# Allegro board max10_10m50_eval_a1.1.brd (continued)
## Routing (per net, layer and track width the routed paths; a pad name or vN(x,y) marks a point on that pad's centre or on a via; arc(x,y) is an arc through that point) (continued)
OV10640_CMOS_SCLK: length 57.4
  TOP w0.147: U1.P5 v1(49.51,35.46)
  ART04 w0.109: v1(49.51,35.46) 50.05,34.92 52.96,34.92 53.89,33.99 53.89,23.83 54.36,23.37 54.36,22.73 54.66,22.43 60.15,22.43 60.71,22.99 65.15,22.99 69.34,18.8 69.34,17.4 69.85,16.89 74.68,16.89 75.44,17.65 80.39,17.65 81.41,18.67 82.93,18.67 83.69,19.43 83.69,20.57 v2(82.55,21.72)
  BOTTOM w0.147: J2.25 81.48,22.15 81.92,21.72 v2(82.55,21.72) R92.2
OV10640_CMOS_SDATA: length 44.4
  TOP w0.147: U1.N8 v1(52.51,35.46)
  ART04 w0.109: v1(52.51,35.46) 52.89,35.84 53.82,35.84 53.98,35.69 53.98,35.43 54.89,34.52 54.89,32.38 55.27,32 55.75,32 55.89,31.87 55.89,29.47 54.74,28.32 54.74,24.51 55.37,23.88 65.66,23.88 67.56,21.97 67.56,21.46 71.25,17.78 v2(73.03,17.78)
  BOTTOM w0.147: J2.24 76.37,22.65 75.31,21.59 75.31,21.08 74.42,20.19 R89.2 73.6,19.81 72.77,18.99 72.77,18.03 v2(73.03,17.78)
OV10640_DATA_HS_N1: length 24.2
  TOP w0.132: U1.AB21 66.02,26.8 66.47,26.34 67.24,26.34 67.36,26.47 67.7,26.47 67.82,26.34 68,26.34 68.4,26.74 68.4,27.23 68.17,27.46 68.17,27.79 68.4,28.01 68.4,28.3 68.17,28.52 68.17,28.88 68.4,29.11 68.4,29.31 68.17,29.54 68.17,29.9 68.4,30.12 68.4,30.45 68.17,30.68 68.17,31.1 68.58,31.5 68.58,31.88 68.83,32.13 69.23,32.13 69.47,32.37 69.47,32.66 69.7,32.89 69.99,32.89 70.28,33.17 70.87,33.17 70.97,33.27 71.37,33.27 71.47,33.17 72.74,33.17 R83.1 73.7,33.17 73.94,33.17 v1(74.3,33.53) 74.62,33.2 75.87,33.2 78.29,30.79 78.67,30.79 v1(78.74,30.86)
  BOTTOM w0.132: v1(78.74,30.86) 79.25,30.35 79.94,30.35 J2.9 ; R86.1 73.6,33.52 73.85,33.27 74.04,33.27 v1(74.3,33.53)
OV10640_DATA_HS_N2: length 25.3
  TOP w0.132: v1(78.61,27.05) 78.49,27.18 78.11,27.18 76.71,25.78 75.69,25.78 75.13,26.34 75.13,27.12 74.95,27.3 74.55,27.3 v1(74.3,27.05) 73.94,27.4 73.7,27.4 R90.1 72.74,27.4 70.31,27.4 70.1,27.2 70.1,26.03 68.45,24.38 66.04,24.38 65.15,23.49 64.39,23.49 63.75,24.13 63.75,25.21 64.25,25.71 64.25,26.73 U1.AB19
  BOTTOM w0.132: v1(74.3,27.05) 74.04,27.3 73.72,27.3 R93.1 ; v1(78.61,27.05) 78.71,27.15 J2.15
OV10640_DATA_HS_N3: length 27
  TOP w0.132: U1.AB17 62.3,26.68 62.3,23.44 63.32,22.42 63.77,21.97 65.53,21.97 66.24,22.68 67,22.68 67.71,21.97 68.45,21.97 69.72,23.24 69.72,23.88 70.58,24.74 72.74,24.74 R76.1 73.7,24.74 73.94,24.74 v1(74.3,24.38) 74.63,24.72 74.87,24.72 75.84,23.75 76.45,23.75 78.2,25.5 78.51,25.5 v1(78.61,25.4)
  BOTTOM w0.132: v1(78.61,25.4) 78.1,25.91 77.6,25.91 J2.18 ; v1(74.3,24.38) 74.04,24.64 73.72,24.64 R78.1
OV10640_DATA_HS_N4: length 28.2
  TOP w0.132: U1.AB16 61.05,26.93 61.05,26.38 60.83,26.16 60.83,25.87 61.05,25.65 61.05,25.27 60.83,25.06 60.83,24.72 61.05,24.51 61.05,22.9 61.85,22.1 61.85,21.84 62.23,21.46 62.48,21.46 63.3,20.65 68.91,20.65 70.33,22.07 72.74,22.07 R84.1 73.7,22.07 73.94,22.07 v1(74.3,21.72) 74.75,22.17 74.99,22.17 75.31,21.84 76.71,21.84 77.6,22.73 77.6,23.11 78.33,23.85 78.51,23.85 v1(78.61,23.75)
  BOTTOM w0.132: v1(78.61,23.75) 79.01,24.15 J2.21 ; v1(74.3,21.72) 74.04,21.97 73.72,21.97 R85.1
OV10640_DATA_HS_P1: length 24.8
  TOP w0.132: U1.AA20 65.53,27.45 65.53,26.67 66.29,25.91 68.18,25.91 68.83,26.56 68.83,31.12 70.46,32.74 72.74,32.74 R81.2 73.7,32.74 73.94,32.74 v1(74.3,32.38) 74.68,32.77 75.69,32.77 78.11,30.35 78.61,30.35 v1(78.74,30.23)
  BOTTOM w0.132: J2.8 77.5,30.81 78.16,30.81 v1(78.74,30.23) ; R79.1 73.72,32.64 74.04,32.64 v1(74.3,32.38)
OV10640_DATA_HS_P2: length 24.7
  TOP w0.132: v1(78.61,27.69) 78.54,27.61 77.92,27.61 76.53,26.22 75.87,26.22 75.56,26.53 75.56,27.3 75.13,27.74 74.75,27.74 v1(74.3,28.19) 73.94,27.84 73.7,27.84 R88.2 72.74,27.84 70.13,27.84 69.67,27.38 69.67,26.22 68.27,24.82 65.86,24.82 64.97,23.93 64.57,23.93 64.19,24.31 64.19,25.03 64.68,25.53 64.68,26.63 U1.AB20
  BOTTOM w0.132: R87.1 73.72,27.94 74.04,27.94 v1(74.3,28.19) ; J2.14 77.61,27.38 78.31,27.38 v1(78.61,27.69)
OV10640_DATA_HS_P3: length 26.6
  TOP w0.132: U1.AB18 62.74,26.69 62.74,26.16 62.87,26.03 62.87,25.53 62.74,25.4 62.74,25.02 62.87,24.89 62.87,24.26 62.74,24.13 62.74,23.62 62.99,23.37 63.25,23.37 63.63,22.99 63.63,22.73 63.95,22.41 65.35,22.41 66.06,23.11 67.18,23.11 67.89,22.41 68.27,22.41 69.29,23.42 69.29,24.06 70.4,25.17 72.74,25.17 R74.2 73.7,25.17 73.94,25.17 v1(74.3,25.53) 74.67,25.15 75.05,25.15 76.02,24.19 76.27,24.19 78.02,25.94 78.51,25.94 v1(78.61,26.03)
  BOTTOM w0.132: v1(78.61,26.03) 80.02,26.03 J2.17 ; v1(74.3,25.53) 74.04,25.27 73.72,25.27 R72.1
OV10640_DATA_HS_P4: length 28.1
  TOP w0.132: U1.AA16 61.48,27.5 61.48,23.08 62.09,22.47 63.48,21.08 68.72,21.08 70.15,22.51 72.74,22.51 R82.2 73.7,22.51 73.94,22.51 v1(74.3,22.86) 74.55,22.61 75.17,22.61 75.49,22.28 76.53,22.28 77.16,22.91 77.16,23.29 78.15,24.28 78.51,24.28 v1(78.61,24.38)
  BOTTOM w0.132: J2.20 77.58,24.89 78.44,24.89 78.61,24.71 v1(78.61,24.38) ; R80.1 73.72,22.61 74.04,22.61 v1(74.3,22.86)
OV10640_DATA_LP_N1: length 13.6
  TOP w0.147: U1.N22 68.68,35.96 69.98,34.67 v1(70.74,34.67)
  BOTTOM w0.147: R86.2 72.71,35.12 72.9,35.31 73.41,35.31 73.79,34.92 74.3,34.92 74.55,35.18 74.55,35.77 74.38,35.94 72.26,35.94 72.01,35.69 72.01,34.8 71.88,34.67 TP48.1 v1(70.74,34.67)
OV10640_DATA_LP_N2: length 11.3
  TOP w0.147: U1.V22 67.56,30.42 v1(67.56,29.46)
  BOTTOM w0.147: v1(67.56,29.46) 67.56,29.06 67.74,28.88 68,28.88 68.2,29.08 68.2,29.72 68.33,29.84 68.58,29.84 68.71,29.72 TP54.1 69.72,28.83 69.98,28.58 69.98,28.32 70.1,28.19 70.74,28.19 70.87,28.32 70.87,28.58 71.09,28.8 71.91,28.8 72.14,28.58 72.14,27.29 72.25,27.18 R93.2
OV10640_DATA_LP_N3: length 10.2
  TOP w0.147: U1.W22 v1(66.52,29.47)
  BOTTOM w0.147: v1(66.52,29.47) 67.06,28.92 67.06,28.32 67.44,27.94 68.45,27.94 68.96,27.43 TP60.1 68.96,26.98 70.03,25.91 70.99,25.91 71.22,26.14 71.78,26.14 72.14,25.78 72.14,25.08 R78.2
OV10640_DATA_LP_N4: length 10
  TOP w0.147: v1(67.82,27.18) 67.8,27.18 U1.AA22
  BOTTOM w0.147: v1(67.82,27.18) 67.82,26.42 68.96,25.27 TP66.1 70.1,23.11 70.87,23.11 71.22,23.47 71.78,23.47 72.14,23.11 72.14,22.42 R85.2
OV10640_DATA_LP_P1: length 14
  TOP w0.147: U1.P21 66.52,35.47 68.04,35.47 68.33,35.18 68.33,34.04 68.71,33.66 69.58,33.66 69.72,33.8 69.72,34.02 69.58,34.16 68.98,34.16 68.83,34.31 68.83,34.52 68.98,34.67 v1(69.34,34.67)
  BOTTOM w0.147: v1(69.34,34.67) TP45.1 70.45,34.19 71.85,34.19 72.14,33.91 72.14,31.88 72.35,31.66 72.56,31.66 72.71,31.81 R79.2
OV10640_DATA_LP_P2: length 11.4
  TOP w0.147: U1.V21 v1(66.52,30.47)
  BOTTOM w0.147: R87.2 72.71,28.77 72.39,29.08 70.48,29.08 70.23,29.34 TP50.1 69.47,29.34 69.22,29.59 69.22,30.1 68.71,30.61 68.22,30.61 68.07,30.46 68.07,30.23 67.94,30.1 67.71,30.1 67.56,30.25 67.56,30.48 67.44,30.61 67.18,30.61 67.06,30.48 67.06,30.1 66.93,29.97 66.04,29.97 65.91,30.1 65.91,30.35 66.03,30.47 v1(66.52,30.47)
OV10640_DATA_LP_P3: length 9.7
  TOP w0.147: U1.Y22 v1(67.52,28.47)
  BOTTOM w0.147: R72.2 72.71,25.84 72.88,26.02 73.26,26.02 73.39,26.14 73.39,26.43 73.15,26.67 72.26,26.67 72.03,26.44 70.1,26.44 69.85,26.7 TP57.1 69.85,27.69 69.22,28.32 68.07,28.32 67.93,28.47 v1(67.52,28.47)
OV10640_DATA_LP_P4: length 10.5
  TOP w0.147: v1(66.52,28.47) U1.AA21
  BOTTOM w0.147: R80.2 72.71,23.05 71.98,23.77 70.33,23.77 TP63.1 69.85,25.27 68.45,26.67 68.45,27.18 68,27.64 67.07,27.64 66.52,28.19 v1(66.52,28.47)
OV10640_FSIN: length 43.1
  TOP w0.147: U1.P8 v1(52.51,34.46)
  ART04 w0.109: v2(75.44,16.64) 75.31,16.51 69.47,16.51 68.83,17.14 68.83,18.8 65.15,22.48 61.59,22.48 60.58,21.46 54.74,21.46 53.85,22.35 53.85,22.86 52.96,23.75 52.96,28.45 53.14,28.63 53.14,29.64 53.47,29.97 53.47,31.55 53.14,31.88 53.14,33.84 v1(52.51,34.46)
  BOTTOM w0.147: J2.32 76.31,18.65 76.07,18.41 76.07,17.91 75.44,17.27 v2(75.44,16.64)
OV10640_G_RDY: length 49.3
  TOP w0.147: U1.R4 v1(48.51,33.46)
  ART04 w0.109: v1(48.51,33.46) 48.83,33.46 49.4,32.89 49.4,32.13 50.04,31.5 50.04,22.99 53.34,19.69 61.85,19.69 62.74,20.57 65.15,20.57 67.31,18.41 67.31,16.38 68.58,15.11 73.41,15.11 v2(73.91,14.61)
  BOTTOM w0.147: J2.28 76.4,20.65 75.31,19.56 75.31,18.29 74.55,17.53 74.55,16.26 73.91,15.62 v2(73.91,14.61)
OV10640_GYRO_INT: length 49.6
  TOP w0.147: U1.N9 v1(53.51,35.46)
  ART04 w0.109: v2(82.55,20.83) 83.06,20.32 83.06,19.69 82.8,19.43 81.15,19.43 79.88,18.16 74.95,18.16 74.1,17.32 71.33,17.32 65.15,23.49 54.99,23.49 54.36,24.13 54.36,28.58 54.99,29.21 54.99,31.75 54.74,32 54.32,32 54.12,32.2 54.12,34.86 v1(53.51,35.46)
  BOTTOM w0.147: J2.27 81.34,21.15 81.66,20.83 v2(82.55,20.83)
OV10640_XM_INT1: length 49.4
  TOP w0.147: U1.R7 v1(51.51,33.46)
  ART04 w0.109: v2(81.92,18.16) 80.58,16.83 77.34,16.83 76.64,16.13 69.34,16.13 68.45,17.02 68.45,18.71 65.19,21.97 61.85,21.97 60.83,20.95 54.35,20.95 53.72,21.59 53.31,21.59 53.08,21.81 53.08,22.35 52.45,22.98 52.45,28.58 52.89,29.01 52.89,30.93 52.07,31.75 52.07,32.91 v1(51.51,33.46)
  BOTTOM w0.147: J2.31 80.93,19.15 v2(81.92,18.16)
OV10640_XM_INT2: length 47.6
  TOP w0.147: U1.R5 v1(49.51,34.46)
  ART04 w0.109: v2(74.93,15.49) 74.68,15.75 69.22,15.75 68.07,16.89 68.07,18.61 65.22,21.46 62.1,21.46 61.21,20.57 53.72,20.57 51.94,22.35 51.94,31.24 51.12,32.06 51.12,33.59 50.8,33.91 50.07,33.91 v1(49.51,34.46)
  BOTTOM w0.147: v2(74.93,15.49) 74.93,17.27 75.69,18.03 75.69,19.05 76.29,19.65 J2.30
PMODA_D0: length 51.2
  TOP w0.147: v2(48.51,70.1) 48.51,70.59 48.66,70.74 49.28,70.74 49.4,70.61 49.4,69.62 49.55,69.47 49.76,69.47 49.91,69.62 49.91,71.1 49.76,71.25 45.87,71.25 45.72,71.1 45.72,70.91 45.87,70.76 47.73,70.76 47.88,70.61 47.88,70.36 47.77,70.25 46.76,70.25 46.61,70.1 46.61,69.85 46.74,69.72 47.75,69.72 49.78,67.69 49.78,62.64 48.26,61.12 48.26,50.93 50.42,48.77 50.42,48.56 U1.A6
  BOTTOM w0.147: v2(48.51,70.1) 48.51,71.25 49.15,71.88 49.15,72.64 48.26,73.53 48.26,73.89 48.41,74.04 49,74.04 49.15,74.19 49.15,74.55 49.02,74.68 44.83,74.68 44.07,73.91 R156.1
PMODA_D1: length 51.8
  TOP w0.147: U1.E8 v1(52.51,44.47)
  ART04 w0.109: v2(43.69,72.14) 53.47,72.14 53.72,71.88 53.72,70.87 55.24,69.34 55.72,69.34 55.83,69.23 55.83,68.57 55.95,68.45 56.18,68.45 56.3,68.57 56.3,69.23 56.42,69.34 56.65,69.34 56.77,69.23 56.77,68.57 56.89,68.45 57.12,68.45 57.24,68.57 57.24,69.23 57.35,69.34 58.17,69.34 60.45,67.06 60.45,62.48 59.31,61.34 56.13,61.34 55.12,60.32 55.12,54.74 55.37,54.48 55.37,51.69 55.12,51.43 55.12,49.78 53.09,47.75 53.09,45.04 v1(52.51,44.47)
  BOTTOM w0.147: v2(43.69,72.14) R157.1
PMODA_D2: length 50.9
  TOP w0.147: v2(41.4,68.45) 43.05,66.8 43.05,63.25 42.42,62.61 41.02,62.61 40.39,61.98 40.39,58.19 40.53,58.04 42.04,58.04 42.16,57.91 42.16,57.66 42.04,57.53 40.53,57.53 40.39,57.38 40.39,57.17 40.53,57.02 42.02,57.02 42.16,56.88 42.16,56.66 42.02,56.52 40.53,56.52 40.39,56.37 40.39,56.17 40.53,56.03 42.02,56.03 42.16,55.88 42.16,55.67 42.02,55.52 40.53,55.52 40.39,55.37 40.39,55.14 40.53,54.99 42.16,54.99 42.67,55.5 42.67,57.78 43.56,58.67 43.56,59.94 44.07,60.45 45.85,60.45 46.74,59.56 46.74,50.42 48.51,48.64 48.51,47.47 U1.B4
  BOTTOM w0.147: R160.1 v2(41.4,68.45)
PMODA_D3: length 51.1
  TOP w0.147: U1.A5 50.01,48.66 47.88,50.8 47.88,61.28 49.4,62.8 49.4,67.44 47.62,69.22 46.61,69.22 45.34,70.48 40.64,70.48 39.88,69.72 35.94,69.72 35.81,69.85 35.81,70.08 35.96,70.23 39.48,70.23 39.62,70.38 39.62,70.61 39.48,70.76 35.96,70.76 35.81,70.91 35.81,71.1 35.96,71.25 v2(41.4,71.25)
  BOTTOM w0.147: R163.1 v2(41.4,71.25)
PMODA_D4: length 51.6
  TOP w0.147: v2(49.02,69.22) 50.16,68.07 50.16,62.48 48.64,60.96 48.64,51.18 48.9,50.93 49.91,50.93 51.52,49.32 51.52,47.46 U1.B7
  BOTTOM w0.147: v2(49.02,69.22) 49.02,70.61 50.04,71.63 51.92,71.63 52.07,71.78 52.07,72.12 51.92,72.26 49.8,72.26 49.66,72.41 49.66,72.88 49.8,73.02 51.92,73.02 52.07,73.17 52.07,73.51 51.92,73.66 49.8,73.66 49.66,73.81 49.66,74.27 49.8,74.42 51.94,74.42 52.07,74.55 52.07,74.93 51.94,75.06 44.32,75.06 44.07,74.8 R158.2
PMODA_D5: length 52.9
  TOP w0.147: U1.E9 v1(53.51,44.47)
  ART04 w0.109: v2(43.69,73.02) 44.2,72.52 54.99,72.52 55.24,72.26 55.24,71.24 55.13,71.12 54.85,71.12 54.74,71.24 54.74,71.89 54.62,72.01 54.35,72.01 54.23,71.89 54.23,70.99 55.37,69.85 58.17,69.85 60.83,67.18 60.83,62.36 59.47,60.99 56.29,60.99 55.72,60.42 55.72,60.37 55.72,49.75 53.51,47.55 v1(53.51,44.47)
  BOTTOM w0.147: v2(43.69,73.02) R159.2
PMODA_D6: length 53.9
  TOP w0.147: v2(41.4,69.47) 41.78,69.09 45.06,69.09 45.21,68.94 45.21,68.6 45.06,68.45 42.69,68.45 42.55,68.31 42.55,67.97 42.69,67.82 45.47,67.82 45.72,67.56 45.72,63.37 44.96,62.61 43.18,62.61 42.73,62.16 41.17,62.16 41.02,62.02 41.02,61.87 41.17,61.72 42.4,61.72 42.55,61.57 42.55,61.36 42.4,61.21 41.04,61.21 40.89,61.07 40.89,60.85 41.04,60.71 42.4,60.71 42.55,60.56 42.55,60.35 42.4,60.2 41.04,60.2 40.89,60.05 40.89,59.84 41.04,59.69 42.4,59.69 42.55,59.54 42.55,59.33 42.4,59.18 41.04,59.18 40.89,59.03 40.89,58.82 41.04,58.67 42.67,58.67 43.05,59.05 43.05,60.2 43.81,60.96 45.97,60.96 47.12,59.82 47.12,50.55 49.01,48.65 U1.A4
  BOTTOM w0.147: v2(41.4,69.47) R161.2
PMODA_D7: length 51
  TOP w0.147: v2(40.64,69.47) 41.15,69.98 45.21,69.98 46.48,68.71 47.48,68.71 47.62,68.56 47.62,68.22 47.48,68.07 46.38,68.07 46.23,67.92 46.23,67.71 46.38,67.56 48.26,67.56 49.02,66.8 49.02,63.27 48.87,63.12 48.66,63.12 48.51,63.27 48.51,66.53 48.37,66.67 48.15,66.67 48.01,66.53 48.01,62.48 47.62,62.1 43.58,62.1 43.43,61.96 43.43,61.59 43.56,61.47 46.23,61.47 47.5,60.2 47.5,50.67 49.51,48.66 49.51,47.47 U1.B5
  BOTTOM w0.147: R164.2 41.53,70.36 v2(40.64,69.47)
PMODA_IO0: length 15.1
  BOTTOM w0.147: J8.1 35.56,65.15 35.56,67.06 37.08,68.58 37.08,70.74 37.67,71.32 39.48,71.32 39.68,71.52 U9.3 39.68,72.82 40.78,73.91 R156.2
PMODA_IO1: length 10.9
  BOTTOM w0.147: J8.2 38.1,65.15 38.1,67.12 39.68,68.71 U9.4 39.68,70.22 40.97,71.5 40.97,71.83 41.27,72.14 R157.2
PMODA_IO2: length 9.7
  BOTTOM w0.147: U8.6 45.02,69.42 44.06,68.45 R160.2 42.99,68.01 42.67,67.69 41.27,67.69 40.64,67.06 40.64,65.15 J8.3
PMODA_IO3: length 21.4
  BOTTOM w0.147: J8.4 43.18,65.15 43.18,67.06 43.69,67.56 46.86,67.56 48.01,68.71 48.01,72.9 46.61,74.3 45.47,74.3 45.02,73.85 U8.1 44.48,72.42 44.32,72.26 44.32,71.75 43.81,71.25 R163.2
PMODA_IO4: length 13.9
  BOTTOM w0.147: R158.1 38.73,74.8 37.79,73.85 U9.1 37.29,72.42 36.7,71.83 36.7,68.83 J8.7
PMODA_IO5: length 10.4
  BOTTOM w0.147: J8.8 36.83,67.56 37.79,68.52 U9.6 37.79,70.75 37.97,70.94 39.95,70.94 40.51,71.5 40.51,72.26 41.27,73.02 R159.1
PMODA_IO6: length 11.5
  BOTTOM w0.147: U8.4 46.92,70.75 46.74,70.94 44.58,70.94 44.2,70.56 44.2,70.1 43.56,69.47 R161.1 42.99,69.15 42.8,68.96 40.89,68.96 39.37,67.44 J8.9
PMODA_IO7: length 16.2
  BOTTOM w0.147: J8.10 43.43,67.95 46.74,67.95 47.62,68.83 47.62,72.22 47.42,72.42 U8.3 46.92,71.47 46.77,71.32 44.45,71.32 43.48,70.36 R164.1
PMODB_D0: length 77.9
  TOP w0.137: U1.C8 v1(52.51,46.47)
  ART04 w0.109: v1(52.51,46.47) 52.51,47.82 54.61,49.91 54.61,51.69 54.99,52.07 54.99,54.23 54.74,54.48 54.74,60.45 55.97,61.68 59.14,61.68 59.82,62.36 59.82,64.64 59.18,65.28 58.55,65.28 52.2,71.63 43.43,71.63 42.16,72.9 34.29,72.9 32.89,74.3 26.92,74.3 25.65,73.02 23.5,73.02 23.24,73.28 23.24,74.42 22.61,75.06 16.26,75.06 15.11,73.91 v2(15.11,71.88)
  BOTTOM w0.147: R171.1 v2(15.11,71.88)
PMODB_D1: length 76.2
  TOP w0.147: U1.D8 v1(52.51,45.47)
  ART04 w0.109: v2(15.62,73.66) 16.64,74.68 22.35,74.68 22.73,74.3 22.73,73.28 23.37,72.64 25.91,72.64 27.18,73.91 32.64,73.91 34.04,72.52 41.78,72.52 43.05,71.25 50.8,71.25 57.28,64.77 58.93,64.77 59.44,64.26 59.44,62.48 59.05,62.1 59.05,62.1 58.99,62.05 55.83,62.05 54.36,60.58 54.36,53.99 54.61,53.74 54.61,52.32 54.1,51.82 54.1,50.04 52.07,48.01 52.07,45.91 v1(52.51,45.47)
  BOTTOM w0.147: v2(15.62,73.66) R173.1
PMODB_D2: length 51.9
  TOP w0.147: v2(15.11,70.99) 26.04,70.99 29.72,67.31 31.88,67.31 32,67.44 35.05,67.44 35.69,66.8 35.69,65.91 36.45,65.15 37.47,65.15 38.1,64.52 38.1,62.61 37.08,61.59 37.08,54.74 37.34,54.48 39.12,54.48 40.64,52.96 40.64,51.98 42.07,50.55 46.1,50.55 48.01,48.63 U1.A3
  BOTTOM w0.147: R175.1 v2(15.11,70.99)
PMODB_D3: length 53.7
  TOP w0.147: U1.A2 46.11,48.87 44.99,48.87 44.58,49.28 42.04,49.28 39.62,51.69 39.62,52.58 38.61,53.59 36.83,53.59 36.07,54.36 36.07,61.34 34.67,62.74 33.27,62.74 30.23,65.79 28.45,65.79 28.19,66.04 28.19,67.31 25.78,69.72 16.26,69.72 15.75,69.22 14.73,69.22 13.08,70.87 13.08,72.26 v2(12.32,73.02)
  BOTTOM w0.147: R177.1 12.32,73.34 v2(12.32,73.02)
PMODB_D4: length 50.2
  TOP w0.147: v2(15.11,69.85) 15.62,70.36 25.91,70.36 29.59,66.67 30.35,66.67 31.88,65.15 35.18,65.15 35.56,64.77 35.56,62.74 36.58,61.72 36.58,54.61 37.21,53.98 38.86,53.98 40.13,52.7 40.13,51.82 42.04,49.91 46.23,49.91 47.51,48.62 47.51,47.47 U1.B3
  BOTTOM w0.147: v2(15.11,69.85) 14.86,70.1 R172.2
PMODB_D5: length 51.5
  TOP w0.147: v2(12.83,68.33) 13.72,67.44 18.16,67.44 18.8,68.07 24.89,68.07 26.04,66.93 26.04,66.29 25.78,66.04 25.78,65.28 27.69,63.37 29.59,63.37 31.88,61.09 33.53,61.09 34.04,60.58 34.04,53.59 35.18,52.45 36.96,52.45 38.23,51.18 38.23,48.77 38.61,48.39 40.39,48.39 41.27,47.5 43.18,47.5 44.21,46.47 46.51,46.47 U1.C2
  BOTTOM w0.147: R174.2 v2(12.83,68.33)
PMODB_D6: length 49.1
  TOP w0.147: v2(12.83,69.22) 14.1,67.95 17.65,67.95 18.29,68.58 25.15,68.58 26.8,66.93 26.8,65.28 28.19,63.88 30.23,63.88 32.38,61.72 33.78,61.72 34.54,60.96 34.54,53.85 35.56,52.83 37.47,52.83 38.73,51.56 38.73,51.31 40.13,49.91 40.13,49.66 41.78,48.01 43.69,48.01 44.73,46.97 U1.B1
  BOTTOM w0.147: R176.2 v2(12.83,69.22)
PMODB_D7: length 52.5
  TOP w0.147: U1.B2 46.51,47.47 45.37,47.47 44.2,48.64 42.04,48.64 39.12,51.56 39.12,52.07 37.97,53.21 36.32,53.21 35.05,54.48 35.05,61.21 34.04,62.23 32.64,62.23 29.97,64.9 28.45,64.9 27.56,65.79 27.56,67.06 25.4,69.22 16.89,69.22 16.26,68.58 14.48,68.58 12.45,70.61 v2(12.45,71.63)
  BOTTOM w0.147: v2(12.45,71.63) 12.91,72.09 12.91,72.16 R178.2
PMODB_IO0: length 18.8
  BOTTOM w0.147: J9.1 10.29,63.88 8.76,65.41 8.76,73.53 8.89,73.66 9.27,73.66 9.46,73.47 U10.1 9.46,71.46 9.6,71.32 11.99,71.32 12.19,71.12 12.76,71.12 R171.2
PMODB_IO1: length 23.8
  BOTTOM w0.147: R173.2 12.95,73.09 12.95,72.77 12.6,72.42 U10.3 11.36,73.98 11.05,74.3 8.76,74.3 8.26,73.79 8.26,65.02 10.54,62.74 12.83,62.74 J9.2
PMODB_IO2: length 16.7
  BOTTOM w0.147: R175.2 13.13,70.6 12.08,70.6 11.73,70.94 9.69,70.94 9.46,70.72 U10.6 9.46,66.61 10.92,65.15 15.24,65.15 J9.3
PMODB_IO3: length 15.7
  BOTTOM w0.147: R177.2 17.27,74.55 18.22,73.6 U11.6 18.89,72.42 20.32,70.99 20.32,65.15 J9.4
PMODB_IO4: length 5.7
  BOTTOM w0.147: R172.1 12.7,70.1 12.42,69.82 U10.4 11.36,67.56 11.43,67.5 J9.7
PMODB_IO5: length 4.9
  BOTTOM w0.147: J9.8 14.41,66.87 R174.1 14.41,68.45 15.37,68.45 16.32,69.41 U11.3
PMODB_IO6: length 10.4
  BOTTOM w0.147: J9.9 18.22,68.13 U11.1 18.22,70.81 18.01,71.02 16.03,71.02 15.62,70.61 15.62,69.47 15.37,69.22 R176.1
PMODB_IO7: length 10.5
  BOTTOM w0.147: J9.10 19.05,70.99 18.72,71.32 16.5,71.32 16.32,71.5 U11.4 15.85,72.42 15.49,72.77 R178.1
SI5338_INTR: length 10.6
  TOP w0.147: U4.A1 23.81,53.66 23.81,56.07 v2(23.62,56.26)
  BOTTOM w0.147: U14.8 22.72,56 22.99,56.26 v2(23.62,56.26) 23.62,56.64 23.81,56.83 R205.1
SI5338A_XTAL_25M_N: length 3.3
  BOTTOM w0.147: Y2.1 18.8,59.66 18.8,58.99 C89.2 18.8,58.36 18.8,57.8 18.93,57.66 U14.2
SI5338A_XTAL_25M_P: length 4.7
  BOTTOM w0.147: U14.1 18.44,57.66 18.49,57.72 18.49,58.28 C87.2 18.41,58.99 18.41,60.58 18.16,60.83 18.01,60.83 Y2.3
TMDS_CLK_N: length 16.4
  TOP w0.114: U3.17 72.47,57.94 76.67,57.94 79.52,60.79 79.98,60.79 80.15,60.62 D1.1 80.86,60.62 81.03,60.79 81.49,60.79 82.55,61.85 82.55,63.64 83.03,64.11 83.39,64.11 83.73,63.77 J4.12
TMDS_CLK_P: length 16.4
  TOP w0.114: J4.10 83.74,64.77 83.4,64.43 82.89,64.43 82.23,63.77 82.23,61.98 81.36,61.1 80.98,61.1 80.81,61.27 D1.2 80.15,61.27 79.98,61.1 79.39,61.1 76.54,58.25 72.47,58.25 U3.18
TMDS_DATA_N0: length 16.4
  TOP w0.114: J4.9 83.73,65.27 83.39,65.61 83.14,65.61 81.79,64.26 81.79,62.48 81.39,62.09 81.03,62.09 80.86,61.92 D1.3 80.15,61.92 79.98,62.09 79.3,62.09 76.65,59.44 72.47,59.44 U3.20
TMDS_DATA_N1: length 16.4
  TOP w0.114: U3.23 72.47,60.94 73.51,60.94 74.04,61.47 74.04,61.98 75.25,63.18 78.3,63.18 79.31,64.2 79.31,65.02 79.52,65.23 79.98,65.23 80.15,65.06 D2.1 80.86,65.06 81.03,65.23 81.61,65.23 82.8,66.42 82.8,66.86 83.06,67.11 83.39,67.11 83.73,66.77 J4.6
TMDS_DATA_N2: length 16.4
  TOP w0.114: J4.3 83.73,68.27 83.39,68.61 82.71,68.61 82.04,67.95 82.04,67.06 81.52,66.53 81.03,66.53 80.86,66.37 D2.3 80.15,66.37 79.98,66.53 78.93,66.53 78.61,66.22 78.61,65.34 77.28,64.01 74.93,64.01 73.36,62.44 72.47,62.44 U3.26
TMDS_DATA_P0: length 16.4
  TOP w0.114: U3.21 72.47,59.75 76.52,59.75 79.17,62.4 79.98,62.4 80.15,62.57 D1.4 80.86,62.57 81.03,62.4 81.26,62.4 81.47,62.62 81.47,64.39 83.01,65.93 83.4,65.93 83.74,66.27 J4.7
TMDS_DATA_P1: length 16.4
  TOP w0.114: U3.24 72.47,61.25 73.38,61.25 73.72,61.6 73.72,62.11 75.12,63.5 78.16,63.5 78.99,64.33 78.99,65.15 79.39,65.55 79.98,65.55 80.15,65.71 D2.2 80.86,65.71 81.03,65.55 81.48,65.55 82.49,66.55 82.49,66.99 82.93,67.43 83.4,67.43 83.74,67.77 J4.4
TMDS_DATA_P2: length 16.4
  TOP w0.114: J4.1 83.74,69.27 83.4,68.93 82.58,68.93 81.72,68.08 81.72,67.19 81.39,66.85 81.03,66.85 80.86,67.02 D2.4 80.15,67.02 79.98,66.85 78.8,66.85 78.3,66.35 78.3,65.47 77.15,64.33 74.8,64.33 73.23,62.75 72.47,62.75 U3.27
USB_ADDR0: length 9.7
  TOP w0.147: U4.R20 37.12,43.47 37.62,43.97 U1.E1
USB_ADDR1: length 14.8
  TOP w0.147: v3(37.08,46.23) 36.84,46.47 U4.J20 ; U1.G3 v1(48.51,42.47)
  ART04 w0.109: v3(37.08,46.23) 38.73,44.58 42.29,44.58 42.8,44.07 44.58,44.07 46.68,41.97 U1.G3 v1(48.51,42.47)
USB_CLK: length 56.5
  TOP w0.147: U1.E11 55.51,44.47 v1(55.51,45.47) ; U4.K1 26.54,45.97 v3(26.29,46.22)
  ART04 w0.109: v1(55.51,45.47) 55.01,45.97 54.36,45.97 53.98,45.59 53.98,44.32 53.72,44.07 52.38,44.07 51.94,44.51 51.94,44.83 51.81,44.97 48.31,44.97 48.01,45.27 48.01,45.84 45.85,48.01 45.34,48.01 45.09,48.26 38.74,48.26 37.34,49.66 36.96,49.66 34.16,46.86 33.66,46.86 33.4,47.12 29.84,47.12 28.95,46.22 v3(26.29,46.22) 26.29,47.12 24.13,49.28 24.13,49.53 21.97,51.69 17.02,51.69 15.24,49.91 14.61,49.91 v2(13.97,49.28)
  BOTTOM w0.147: v2(13.97,49.28) 13.97,48.41 14.54,47.84 U7.13
USB_DATA0: length 16.4
  TOP w0.147: U4.H20 36.85,46.97 v3(37.08,46.74) ; U1.H4 v1(49.51,41.47)
  ART04 w0.109: v3(37.08,46.74) 38.86,44.96 42.67,44.96 43.18,44.45 44.83,44.45 46.32,42.97 48.73,42.97 49.01,42.68 49.01,41.97 v1(49.51,41.47)
USB_DATA1: length 9.9
  TOP w0.147: U4.T20 37.25,42.97 37.72,43.43 45.55,43.43 U1.F1
USB_DATA2: length 14.4
  TOP w0.147: U1.E4 v1(48.51,44.47) ; v3(37.08,48.26) 36.87,48.47 U4.E20
  ART04 w0.109: v3(37.08,48.26) 38.48,46.86 44.58,46.86 46.61,44.83 47.75,44.83 48.12,44.47 v1(48.51,44.47)
USB_DATA3: length 11.9
  TOP w0.147: U4.P20 36.98,43.97 37.48,44.47 47.51,44.47 U1.E3
USB_DATA4: length 10.1
  TOP w0.147: U4.V20 37.33,41.97 37.77,41.53 42.11,41.53 42.87,42.29 44,42.29 44.32,41.97 U1.G1
USB_DATA5: length 9.7
  TOP w0.147: U1.H1 42.22,40.97 42.04,41.15 37.53,41.15 37.21,41.47 U4.W20
USB_DATA6: length 13.6
  TOP w0.147: U4.K20 36.83,45.97 v3(37.08,45.72) ; U1.H3 v1(47.51,41.47)
  ART04 w0.109: v1(47.51,41.47) 46.55,41.47 44.45,43.56 42.8,43.56 42.16,44.2 38.61,44.2 v3(37.08,45.72)
USB_DATA7: length 11.9
  TOP w0.147: U4.Y20 37.08,40.97 37.29,40.77 41.66,40.77 41.96,40.47 47.51,40.47 U1.J3
USB_DISABLEN: length 39.3
  TOP w0.147: 7.94,56.52 R147.2 10.99,56.07 11.18,55.88 12.06,55.88 v2(12.7,55.24) ; v3(34.42,48.45) 34.44,48.47 U4.E17
  ART04 w0.109: v3(34.42,48.45) 33.21,49.66 30.99,49.66 30.23,50.42 27.56,50.42 24.26,53.72 24.26,54.48 23.11,55.63 23.11,56.77 21.97,57.91 18.16,57.91 17.4,57.15 16.76,57.15 15.88,56.26 15.88,54.74 14.8,53.66 14.8,53.28 14.1,52.58 12.83,52.58 12.57,52.83 12.57,53.47 13.21,54.1 13.21,54.74 v2(12.7,55.24)
USB_EMPTY: length 14.7
  TOP w0.147: U1.F3 v1(47.51,43.47) ; v3(37.08,47.24) 36.86,47.47 U4.G20
  ART04 w0.109: v3(37.08,47.24) 38.86,45.47 44.7,45.47 46.23,43.94 47.04,43.94 v1(47.51,43.47)
  BOTTOM w0.147: R138.2 46.8,44.18 v1(47.51,43.47)
USB_FULL: length 19.8
  TOP w0.147: U4.F20 36.87,47.97 v3(37.08,47.75) ; U1.F4 v1(48.51,43.47)
  ART04 w0.109: v3(37.08,47.75) 38.35,46.48 44.45,46.48 46.61,44.32 47.66,44.32 v1(48.51,43.47)
  BOTTOM w0.147: R142.2 47.5,47.82 47.5,46.89 47.9,46.48 47.9,44.08 v1(48.51,43.47)
USB_OEN: length 11.1
  TOP w0.147: U1.F2 46.51,42.47 44.96,42.47 44.5,42.93 37.85,42.93 37.39,42.47 U4.U20
USB_RDN: length 15.7
  TOP w0.147: v3(37.08,45.21) 36.83,45.47 U4.L20 ; U1.J4 48.51,40.47 v1(48.51,41.47)
  ART04 w0.109: v1(48.51,41.47) 48.07,41.02 46.35,41.02 44.32,43.05 42.55,43.05 41.91,43.69 38.61,43.69 v3(37.08,45.21)
USB_RESETN: length 12.3
  TOP w0.147: U1.K2 46.51,39.47 41.43,39.47 40.89,40 36.47,40 U4.Y18
USB_SCL: length 13.1
  TOP w0.147: v3(37.08,48.77) 36.88,48.97 U4.D20 ; U1.D2 v1(46.51,45.47)
  ART04 w0.109: v1(46.51,45.47) 44.79,47.19 38.66,47.19 v3(37.08,48.77)
  BOTTOM w0.147: v1(46.51,45.47) 46.8,45.75 R140.2
USB_SDA: length 15.3
  TOP w0.147: U4.C20 36.89,49.47 v3(37.08,49.28) ; U1.D3 v1(47.51,45.47)
  ART04 w0.109: v1(47.51,45.47) 46.74,46.24 46.47,46.24 45.09,47.62 38.73,47.62 v3(37.08,49.28)
  BOTTOM w0.147: v1(47.51,45.47) 47.51,46.4 R141.2
USB_WRN: length 10.4
  TOP w0.147: U4.Y19 36.58,40.39 41.27,40.39 41.7,39.97 U1.J1
USER_CLKIN_IO_N: length 25.1
  TOP w0.114: R268.1 80.55,31.34 80.55,12.54 v1(80.77,12.32)
  BOTTOM w0.114: J12.5 79.98,10.16 80.26,10.45 80.26,10.99 81.22,11.94 81.22,12.76 80.96,13.02 80.71,13.02 80.52,12.83 80.52,12.57 v1(80.77,12.32)
USER_CLKIN_IO_P: length 26
  TOP w0.114: v1(80.01,12.32) 80.23,12.54 80.23,31.34 R179.1
  BOTTOM w0.114: v1(80.01,12.32) 80.2,12.51 80.2,12.96 80.58,13.34 81.09,13.34 81.53,12.9 81.53,11.81 80.58,10.86 80.58,10.48 80.9,10.16 J12.3
USER_CLKIN_N_MAX10: length 19
  TOP w0.114: U1.K21 66.52,39.47 67.66,39.47 68.71,38.42 71.75,38.42 R272.1 72.65,37.52 73.09,37.52 75.95,34.67 80.26,34.67 80.55,34.39 80.55,34.07 R269.2 80.55,33.5 80.55,32.92 R268.2
USER_CLKIN_P: length 12.4
  TOP w0.114: R271.1 71.56,37.34 71.95,37.34 R272.2 72.7,37.21 72.96,37.21 75.81,34.35 80.13,34.35 80.23,34.25 80.23,34.07 R180.2 80.23,33.5 80.23,32.92 R179.2
USER_CLKIN_P_MAX10: length 8
  TOP w0.114: R270.2 R271.2 70.55,37.53 70.74,37.72 71.63,37.72 71.75,37.85 71.75,37.97 71.63,38.1 68.58,38.1 67.53,39.15 67.2,39.15 U1.K22
USER_DIPSW0: length 46.9
  TOP w0.137: U1.R18 v1(63.52,33.46)
  TOP w0.147: SW1.8 v2(90.55,32.38)
  ART04 w0.109: v2(90.55,32.38) 89.09,30.92 89.09,27.5 86.11,24.51 82.68,24.51 77.72,19.56 71.75,19.56 69.85,21.46 69.85,23.49 66.01,27.33 66.01,27.77 66.14,27.89 66.14,32.41 65.53,33.02 63.96,33.02 v1(63.52,33.46)
  BOTTOM w0.147: R181.2 v2(90.55,32.38)
USER_DIPSW1: length 44.4
  TOP w0.147: SW1.7 v2(90.55,31.12) ; U1.T19 v1(64.52,32.46)
  ART04 w0.109: v2(90.55,31.12) 89.53,30.1 89.53,27.3 86.36,24.13 82.93,24.13 78.11,19.3 71.63,19.3 69.47,21.46 69.47,23.24 65.71,27 65.71,27.97 65.89,28.14 65.89,31.62 65.51,32 64.98,32 v1(64.52,32.46)
  BOTTOM w0.147: R182.2 v2(90.55,31.12)
USER_DIPSW2: length 44.2
  TOP w0.147: SW1.6 v2(90.55,29.84) ; U1.T18 v1(63.52,32.46)
  ART04 w0.109: v1(63.52,32.46) 63.98,32 64.52,32 65.13,31.39 65.13,28.09 65.28,27.94 65.28,26.8 69.09,22.99 69.09,21.46 71.5,19.05 78.49,19.05 83.19,23.75 86.61,23.75 90.04,27.18 90.04,29.34 v2(90.55,29.84)
  BOTTOM w0.147: R184.2 v2(90.55,29.84)
USER_DIPSW3: length 42.1
  TOP w0.147: SW1.5 v2(90.55,28.58) ; U1.U19 v1(64.52,31.46)
  ART04 w0.109: v1(64.52,31.46) 64.9,31.08 64.9,26.54 68.71,22.73 68.71,21.46 71.37,18.8 78.87,18.8 83.44,23.37 86.87,23.37 90.55,27.05 v2(90.55,28.58)
  BOTTOM w0.147: v2(90.55,28.58) R185.2
USER_DIPSW4: length 23.7
  TOP w0.147: SW2.8 44.96,59.05 43.18,57.28 43.18,55.12 42.55,54.48 v2(42.55,52.83) 42.42,52.7 R189.2 ; U1.G4 v1(49.51,42.47)
  BOTTOM w0.102: 48.16,46.74 48.16,44.17 48.39,43.94 48.64,43.94 48.9,43.69 48.9,43.09 v1(49.51,42.47)
  BOTTOM w0.147: v2(42.55,52.83) 42.55,52.45 45.09,49.91 46.61,49.91 47.88,48.64 47.88,47.12 48.16,46.84 48.16,46.74
USER_DIPSW5: length 20.7
  TOP w0.147: R190.2 43.31,52.7 v2(43.43,52.83) 43.43,53.34 43.69,53.59 43.69,56.64 44.83,57.78 SW2.7 ; U1.F5 v1(49.51,43.46)
  BOTTOM w0.147: v1(49.51,43.46) 48.9,44.08 48.9,46.74 48.39,47.24 48.39,48.89 46.86,50.42 45.21,50.42 43.43,52.2 v2(43.43,52.83)
USER_IO0: length 38.7
  TOP w0.147: U1.A17 62.02,48.68 v2(62.87,49.53)
  ART04 w0.109: J14.1 61.85,67.69 69.93,67.69 71.88,65.74 71.88,56.64 68.83,53.59 66.93,53.59 v2(62.87,49.53)
USER_IO1: length 38
  TOP w0.147: v2(64.52,49.53) 64.52,47.47 U1.B19
  ART04 w0.109: J14.3 63.63,68.45 71.1,68.45 72.64,66.91 72.64,56.39 69.09,52.83 67.31,52.83 64.52,50.04 v2(64.52,49.53)
USER_IO2: length 40.4
  TOP w0.147: U1.E16 v1(61.52,44.47)
  ART04 w0.109: v1(61.52,44.47) 61.89,44.84 61.89,45.76 62.1,45.97 62.1,46.74 62.36,46.99 63.63,46.99 64.01,47.37 64.01,48.51 64.52,49.02 65.66,49.02 67.94,51.31 68.71,51.31 73.41,56.01 73.41,67.31 73.66,67.56 73.66,68.58 73.28,68.96 72.39,68.96 72.14,69.22 67.94,69.22 J14.7
USER_IO3: length 36.6
  TOP w0.147: U1.C19 v1(64.52,46.47)
  ART04 w0.109: J14.9 69.6,70.1 72.64,70.1 73.03,69.72 73.66,69.72 74.1,69.28 74.49,69.28 75.69,68.07 75.69,60.45 74.93,59.69 74.93,56.26 69.22,50.55 67.89,50.55 65.86,48.51 65.02,48.51 64.52,48.01 64.52,46.84 v1(64.52,46.47)
USER_IO4: length 42
  TOP w0.147: U1.F16 v1(61.52,43.47)
  ART04 w0.109: J14.13 74.3,70.48 74.8,70.48 78.11,67.18 78.11,65.79 77.34,65.02 77.34,54.48 76.33,53.47 73.15,53.47 69.47,49.78 67.89,49.78 65.95,47.84 65.36,47.84 65.14,47.62 65.14,46.08 64.9,45.84 62.36,45.84 62.14,45.62 62.14,44.09 v1(61.52,43.47)
USER_IO5: length 40.8
  TOP w0.147: U1.A19 v1(63.59,48.39)
  ART04 w0.109: J14.2 59.69,72.39 59.69,70.74 62.36,68.07 69.98,68.07 72.26,65.79 72.26,56.52 68.96,53.21 67.06,53.21 63.59,49.75 v1(63.59,48.39)
USER_IO6: length 40.4
  TOP w0.147: U1.A20 65.02,49.14 v2(65.41,49.53)
  ART04 w0.109: v2(65.41,49.53) 65.41,50.29 67.56,52.45 69.22,52.45 73.03,56.26 73.03,67.56 73.28,67.82 73.28,68.42 73.03,68.67 71.79,68.67 71.62,68.83 64.01,68.83 62.23,70.61 62.23,72.39 J14.4
USER_IO7: length 40.9
  TOP w0.147: U1.C18 v1(63.52,46.47)
  ART04 w0.109: v1(63.52,46.47) 64.26,47.21 64.26,48.26 64.77,48.77 65.77,48.77 67.93,50.93 68.83,50.93 73.79,55.88 73.79,62.86 75.31,64.39 75.31,67.95 74.36,68.9 73.98,68.9 73.53,69.34 72.77,69.34 72.52,69.6 68.33,69.6 67.31,70.61 67.31,72.39 J14.8
USER_IO8: length 43.9
  TOP w0.147: U1.C17 v1(62.52,46.47)
  ART04 w0.109: J14.10 69.85,72.39 72.01,72.39 72.52,71.88 72.52,70.87 73.28,70.1 74.42,70.1 76.07,68.45 76.07,60.83 76.71,60.2 76.71,54.48 76.2,53.98 73.15,53.98 69.34,50.16 67.89,50.16 65.86,48.13 65.28,48.13 64.9,47.75 64.9,46.23 64.76,46.09 62.89,46.09 v1(62.52,46.47)
USER_IO9: length 42.1
  TOP w0.147: U1.D17 v1(62.52,45.47)
  ART04 w0.109: J14.14 74.93,72.39 74.93,70.99 78.49,67.44 78.49,65.53 77.72,64.77 77.72,54.23 76.58,53.09 73.28,53.09 69.6,49.4 67.87,49.4 66.04,47.57 66.04,46.23 65.79,45.97 65.41,45.97 65.02,45.59 62.64,45.59 v1(62.52,45.47)
USER_LED0: length 64.8
  TOP w0.147: D3.2 7.04,61.34 7.11,61.34 v2(7.49,61.72) ; U1.C3 v1(48.52,46.47)
  ART04 w0.109: v2(7.49,61.72) 14.22,61.72 14.86,61.09 15.62,61.09 16.26,61.72 20.32,61.72 22.99,59.05 22.99,58.42 24.13,57.28 27.56,57.28 27.94,57.66 28.32,57.66 31.88,61.21 44.83,61.21 48.26,57.78 51.18,57.78 51.56,57.4 51.56,51.56 48.13,48.13 48.13,46.85 v1(48.52,46.47)
USER_LED0_R: length 2.1
  TOP w0.147: v2(3.56,60.32) 4.39,60.32 D3.1
  BOTTOM w0.147: R183.2 v2(3.56,60.32)
USER_LED1: length 64.7
  TOP w0.147: U1.C4 v1(49.52,45.46) ; v2(7.49,62.61) 6.78,62.61 D4.2
  ART04 w0.109: v1(49.52,45.46) 49.02,45.96 49.02,46.61 48.64,46.99 48.64,48.01 51.94,51.31 51.94,57.66 51.44,58.17 48.64,58.17 45.21,61.59 31.5,61.59 28.83,58.93 23.88,58.93 20.7,62.1 8.05,62.1 7.49,62.66 v2(7.49,62.61)
USER_LED1_R: length 2.3
  TOP w0.147: v2(3.56,61.21) 3.94,61.59 4.14,61.59 D4.1
  BOTTOM w0.147: R186.2 v2(3.56,61.21)
USER_LED2: length 64.2
  TOP w0.147: D5.2 6.65,63.5 v2(7.49,63.5) ; U1.C5 v1(49.51,46.47)
  ART04 w0.109: v1(49.51,46.47) 49.51,46.75 49.15,47.12 49.15,47.88 52.32,51.05 52.32,57.91 51.56,58.67 48.77,58.67 45.47,61.98 31.37,61.98 28.7,59.31 24.51,59.31 21.34,62.48 8.51,62.48 v2(7.49,63.5)
USER_LED2_R: length 2.9
  TOP w0.147: v2(3.56,62.1) 4.06,62.61 4.06,63.04 D5.1
  BOTTOM w0.147: R187.2 v2(3.56,62.1)
USER_LED3: length 66.8
  TOP w0.147: U1.D5 v1(50.51,45.47) ; D6.2 7.29,64.39 v2(7.49,64.39)
  ART04 w0.109: v2(7.49,64.39) 9.02,62.86 22.1,62.86 23.88,61.09 23.88,60.71 24.89,59.69 28.45,59.69 31.11,62.36 45.85,62.36 49.02,59.18 51.69,59.18 52.7,58.17 52.7,50.8 49.53,47.62 49.53,47.24 50.04,46.74 50.04,45.94 v1(50.51,45.47)
USER_LED3_R: length 3.5
  TOP w0.147: D6.1 4.06,64.57 4.06,63.5 v2(3.56,62.99)
  BOTTOM w0.147: R188.2 v2(3.56,62.99)
USER_LED4: length 68.7
  TOP w0.147: U1.C7 51.51,46.47 v1(50.51,46.47) ; D7.2 7.49,65.71 v2(7.49,65.28)
  ART04 w0.109: v2(7.49,65.28) 22.23,65.28 22.86,64.64 22.86,63.25 26.04,60.07 28.19,60.07 30.99,62.86 46.99,62.86 49.91,59.94 51.69,59.94 53.09,58.55 53.09,50.67 50.04,47.62 50.04,47.37 50.51,46.89 v1(50.51,46.47)
USER_LED4_R: length 4.1
  TOP w0.147: D7.1 3.56,65.58 v2(3.56,63.88)
  BOTTOM w0.147: R193.2 v2(3.56,63.88)
USER_LVDS_N0: length 38.2
  TOP w0.114: U1.Y10 v1(55.51,28.46)
  BOTTOM w0.114: J12.11 72.39,10.16 72.61,10.38 72.61,11.52 72.32,11.81 68.45,11.81 64.9,15.37 62.1,15.37 59.69,17.78 52.83,17.78 52.2,18.41 52.2,19.43 52.51,19.75 52.51,22.61 54.29,24.39 54.29,25.4 R153.1 54.32,25.94 54.32,26.45 54.67,26.8 54.67,27.82 54.99,28.13 55.37,28.13 55.51,28.27 v1(55.51,28.46)
USER_LVDS_N1: length 41.1
  TOP w0.114: U1.W7 v1(51.51,29.46)
  BOTTOM w0.114: v1(51.51,29.46) 52.07,28.91 52.07,28.64 R154.1 52.17,28.16 52.17,25.31 50.42,23.56 50.42,21.28 49.72,20.58 49.72,17.52 50.73,16.51 52.83,16.51 54.48,14.86 55.12,14.86 55.56,15.3 55.56,16.25 55.77,16.46 56.37,16.46 56.64,16.19 56.64,14.92 57.08,14.48 57.92,14.48 58.36,14.92 58.36,16.19 58.61,16.45 59.18,16.45 59.5,16.13 59.5,14.98 60.19,14.29 64.33,14.29 64.99,13.62 64.99,10.38 64.77,10.16 J12.17
USER_LVDS_N2: length 36.1
  TOP w0.114: U1.AA17 v1(62.51,27.46)
  ART04 w0.084: J12.6 79.97,7.62 80.17,7.82 80.17,10.98 77.82,13.34 67.79,13.34 64.94,16.18 64.94,16.59 v1(64.64,16.89)
  BOTTOM w0.114: v1(64.64,16.89) 64.9,17.14 64.9,17.91 63.44,19.37 63.44,20.58 63.72,20.86 63.72,25.24 R155.1 63.65,25.74 63.65,26.27 62.9,27.02 62.9,27.68 62.77,27.81 62.61,27.81 62.51,27.72 v1(62.51,27.46)
USER_LVDS_N3: length 38
  TOP w0.114: U1.Y13 v1(58.51,28.46)
  ART04 w0.084: J12.12 72.35,7.62 72.62,7.89 72.62,11.06 73.16,11.6 74.94,11.6 75.15,11.81 75.15,12.07 74.94,12.28 67.35,12.28 64.14,15.49 63.5,15.49 63.04,15.96 63.04,16.59 v1(62.74,16.89)
  BOTTOM w0.114: v1(58.51,28.46) 58.86,28.12 58.86,27.69 R162.1 58.9,27.15 58.9,26.7 59.31,26.29 60.83,26.29 62.48,24.64 62.48,21.15 62.04,20.71 62.04,18.99 62.99,18.03 62.99,17.14 v1(62.74,16.89)
USER_LVDS_N4: length 42.1
  TOP w0.114: U1.W9 v1(53.51,29.46)
  ART04 w0.084: 28.83,7.62 29.68,7.62 29.95,7.89 29.95,10.68 31.88,12.61 41.82,12.61 47.54,18.33 50.42,18.33 51.27,19.17 51.27,19.47 v1(51.05,19.69)
  BOTTOM w0.114: v1(51.05,19.69) 51.24,19.88 51.24,22.74 51.44,22.93 51.44,23.24 51.69,23.49 52,23.49 52.32,23.82 52.32,24.13 52.58,24.38 52.89,24.38 53.15,24.64 53.15,25.02 52.96,25.21 52.96,25.65 53.15,25.84 53.15,26.29 53.47,26.61 53.47,26.99 R165.1 53.47,27.62 53.47,27.82 53.91,28.26 53.91,29.07 v1(53.51,29.46)
USER_LVDS_N5: length 42.4
  TOP w0.114: U1.V7 v1(51.51,30.46)
  BOTTOM w0.114: 36.45,10.16 37.34,10.16 37.56,10.38 37.56,11.47 38.1,12 43.37,12 43.94,11.43 43.94,10.16 44.26,9.84 46.73,9.84 47.12,10.23 47.12,13.01 46.79,13.34 46.04,13.34 45.22,12.51 44.57,12.51 44.13,12.95 44.13,18.55 48.7,23.12 48.7,24.64 49.72,25.66 49.72,27.73 50.1,28.11 R166.1 50.89,29.24 50.89,29.74 51.23,30.09 51.78,30.09 51.89,30.2 51.89,30.35 51.78,30.46 v1(51.51,30.46)
USER_LVDS_N6: length 39.9
  TOP w0.114: U1.W5 v1(49.51,29.46)
  BOTTOM w0.114: v1(49.51,29.46) 48.96,28.91 48.96,27.24 48.77,27.05 48.77,26.73 48.96,26.54 48.96,26.2 47.56,24.8 47.56,24.51 R167.1 47.43,23.88 47.43,23.37 42.99,18.93 42.99,13.97 42.48,13.46 41.85,13.46 41.47,13.85 41.47,15.68 40.96,16.19 40.13,16.19 39.56,15.63 39.56,13.72 39.24,13.4 36.83,13.4 35.68,12.26 30.98,12.26 29.94,11.21 29.94,10.38 29.72,10.16 28.83,10.16
USER_LVDS_N7: length 40
  TOP w0.114: U1.W4 v1(48.51,30.47)
  BOTTOM w0.114: v1(48.51,30.47) 48.51,30.23 48.37,30.09 47.99,30.09 47.69,29.78 47.69,27.81 R168.1 47.75,27.24 47.75,26.92 47.94,26.73 47.94,26.29 45.91,24.26 45.91,23.37 40.06,17.53 38.99,17.53 35.12,13.65 30.48,13.65 28.82,12 23.36,12 22.32,10.96 22.32,10.38 22.1,10.16 21.21,10.16
USER_LVDS_N8: length 37.4
  TOP w0.114: U1.AA6 v1(50.51,27.46)
  ART04 w0.084: v1(48.01,17.53) 48.3,17.23 48.3,15.45 48.77,14.99 50.89,14.99 51.31,14.57 51.31,14 50.93,13.63 44.71,13.63 42.55,11.47 38.36,11.47 37.57,10.68 37.57,7.89 37.3,7.62 36.45,7.62
  BOTTOM w0.114: v1(50.51,27.46) 50.83,27.15 50.83,26.63 R169.1 50.89,26.14 50.89,25.56 49.59,24.26 49.59,21.72 48.32,20.45 48.32,17.84 v1(48.01,17.53)
USER_LVDS_P0: length 38.1
  TOP w0.114: U1.AA10 v1(55.51,27.46)
  BOTTOM w0.114: v1(55.51,27.46) 55.51,27.67 55.37,27.81 55.12,27.81 54.99,27.69 54.99,26.67 54.64,26.32 54.64,25.94 R153.2 54.61,25.34 54.61,25.15 54.76,24.99 54.76,24.66 54.61,24.51 54.61,24.26 53.55,23.19 53.55,22.94 53.34,22.73 53.09,22.73 52.83,22.48 52.83,21.72 52.96,21.59 52.96,21.21 52.83,21.08 52.83,19.62 52.51,19.3 52.51,18.55 52.96,18.1 59.82,18.1 62.23,15.68 65.03,15.68 68.58,12.13 72.45,12.13 72.93,11.65 72.93,10.38 73.15,10.16 J12.9
USER_LVDS_P1: length 41
  TOP w0.114: U1.W8 v1(52.51,29.46)
  BOTTOM w0.114: J12.15 65.53,10.16 65.31,10.38 65.31,13.75 64.46,14.61 60.33,14.61 59.82,15.11 59.82,16.26 59.31,16.76 58.48,16.76 58.04,16.32 58.04,15.05 57.78,14.8 57.21,14.8 56.96,15.05 56.96,16.32 56.5,16.78 55.64,16.78 55.24,16.38 55.24,15.44 54.99,15.18 54.61,15.18 52.96,16.83 50.86,16.83 50.04,17.65 50.04,20.45 50.74,21.15 50.74,23.43 52.48,25.18 52.48,28.16 R154.2 52.32,28.89 52.32,29.27 v1(52.51,29.46)
USER_LVDS_P2: length 36.6
  TOP w0.114: U1.Y17 v1(62.51,28.46)
  ART04 w0.084: v1(65.53,16.89) 65.23,16.59 65.23,16.3 67.91,13.63 77.94,13.63 80.47,11.1 80.47,7.94 80.79,7.62 J12.4
  BOTTOM w0.114: v1(62.51,28.46) 63.15,27.83 63.15,27.21 63.96,26.4 63.96,25.89 R155.2 64.04,25.24 64.04,20.73 63.75,20.45 63.75,19.5 65.21,18.04 65.21,17.21 v1(65.53,16.89)
USER_LVDS_P3: length 38
  TOP w0.114: U1.Y14 v1(59.51,28.46)
  ART04 w0.084: J12.10 73.17,7.62 72.92,7.87 72.92,10.94 73.28,11.3 75.06,11.3 75.44,11.68 75.44,12.19 75.06,12.57 67.47,12.57 64.26,15.79 63.62,15.79 63.33,16.08 63.33,16.59 v1(63.63,16.89)
  BOTTOM w0.114: v1(63.63,16.89) 63.31,17.21 63.31,18.17 62.36,19.12 62.36,20.57 62.8,21.02 62.8,24.77 60.96,26.61 59.44,26.61 59.21,26.83 59.21,27.15 R162.2 59.18,27.75 59.18,28.13 v1(59.51,28.46)
USER_LVDS_P4: length 41.4
  TOP w0.114: U1.W10 v1(54.51,29.46)
  ART04 w0.084: 31.37,7.62 30.5,7.62 30.25,7.87 30.25,10.56 32,12.32 41.94,12.32 47.66,18.03 50.55,18.03 51.56,19.05 51.56,19.47 v1(51.78,19.69)
  BOTTOM w0.114: v1(51.78,19.69) 51.56,19.9 51.56,22.61 53.47,24.51 53.47,26.16 53.78,26.48 53.78,27.05 R165.2 53.85,27.5 53.85,27.75 54.23,28.13 54.23,29.18 v1(54.51,29.46)
USER_LVDS_P5: length 42.4
  TOP w0.114: U1.V8 v1(52.51,30.46)
  BOTTOM w0.114: 38.99,10.16 38.1,10.16 37.88,10.38 37.88,11.33 38.23,11.68 43.24,11.68 43.62,11.3 43.62,10.03 44.13,9.53 46.86,9.53 47.43,10.1 47.43,13.14 46.93,13.65 45.91,13.65 45.09,12.83 44.7,12.83 44.45,13.08 44.45,18.41 49.02,22.99 49.02,24.51 50.04,25.53 50.04,27.6 50.38,27.94 50.48,27.94 R166.2 51.13,28.59 51.13,29.64 51.33,29.84 51.88,29.84 52.13,30.1 52.13,30.35 52.25,30.46 v1(52.51,30.46)
USER_LVDS_P6: length 40.3
  TOP w0.114: U1.W6 v1(50.51,29.46)
  BOTTOM w0.114: v1(50.51,29.46) 50.01,28.96 49.46,28.96 49.28,28.78 49.28,26.06 47.88,24.67 47.88,24.32 R167.2 47.75,23.81 47.75,23.24 43.31,18.8 43.31,13.84 42.61,13.14 41.72,13.14 41.15,13.72 41.15,15.55 40.83,15.88 40.26,15.88 39.88,15.49 39.88,13.59 39.37,13.08 36.96,13.08 35.81,11.94 31.11,11.94 30.26,11.08 30.26,10.38 30.48,10.16 31.37,10.16
USER_LVDS_P7: length 39.4
  TOP w0.114: U1.W3 v1(48.52,29.46)
  BOTTOM w0.114: 23.75,10.16 22.86,10.16 22.64,10.38 22.64,10.83 23.5,11.68 28.96,11.68 30.61,13.34 35.25,13.34 39.12,17.21 40.2,17.21 46.23,23.24 46.23,24.13 48.26,26.16 48.26,26.86 48.07,27.05 48.07,27.3 R168.2 48.01,27.88 48.01,29.65 48.12,29.77 48.39,29.77 48.52,29.64 v1(48.52,29.46)
USER_LVDS_P8: length 38.1
  TOP w0.114: U1.AA7 v1(51.51,27.46)
  ART04 w0.084: 38.99,7.62 38.12,7.62 37.87,7.87 37.87,10.56 38.48,11.18 42.67,11.18 44.83,13.34 51.05,13.34 51.6,13.88 51.6,14.69 51.02,15.28 48.89,15.28 48.6,15.57 48.6,17.23 v1(48.9,17.53)
  BOTTOM w0.114: v1(48.9,17.53) 48.64,17.78 48.64,18.03 48.9,18.29 48.9,18.54 48.64,18.8 48.64,19.18 48.9,19.43 48.9,19.69 48.64,19.94 48.64,20.32 49.91,21.59 49.91,24.13 50.29,24.51 50.55,24.51 50.8,24.77 50.8,25.02 51.21,25.43 51.21,26.12 R169.2 51.14,26.77 51.14,27.09 v1(51.51,27.46)
USER_PB0: length 41.8
  TOP w0.147: S1.4 85.09,24.36 v2(85.75,25.02) 86.41,24.36 S1.3 ; U1.R20 v1(65.52,33.46)
  ART04 w0.109: v1(65.52,33.46) 66.09,32.89 66.67,32.89 67.01,32.55 67.01,26.97 70.23,23.75 70.23,21.55 70.58,21.21 70.73,21.21 72.12,19.81 77.34,19.81 82.55,25.02 v2(85.75,25.02)
  BOTTOM w0.147: v2(85.75,25.02) 86.38,24.38 R202.2
USER_PB1: length 36.6
  TOP w0.147: v2(82.55,19.92) 82.55,19.05 83.97,17.63 S2.4 S2.3 ; U1.Y20 v1(64.52,28.46)
  ART04 w0.109: v1(64.52,28.46) 64.52,26.29 68.33,22.48 68.33,21.46 71.25,18.54 79.38,18.54 81.28,20.45 82.02,20.45 v2(82.55,19.92)
  BOTTOM w0.147: R196.2 82.57,19.94 v2(82.55,19.92)
USER_PB2: length 22.5
  TOP w0.147: v2(69.87,17.63) S3.4 71.91,17.14 74.3,17.14 74.93,17.78 76.43,17.78 76.58,17.63 S3.3 ; U1.Y21 v1(65.52,28.46)
  BOTTOM w0.147: v1(65.52,28.46) 65.53,28.45 65.53,27.81 67.18,26.16 67.18,22.86 69.91,20.13 R195.2 69.91,17.67 v2(69.87,17.63)
USER_PB3: length 22.5
  TOP w0.147: S4.4 v2(66.8,17.63) S4.3 ; U1.U20 v1(65.52,31.46)
  BOTTOM w0.147: v1(65.52,31.46) 65.02,30.97 65.02,27.81 66.74,26.1 R198.2 66.74,17.69 v2(66.8,17.63)
VREF_1V2HSTL: length 4.3
  TOP w0.381: U1.P22 v1(67.69,34.96)
  BOTTOM w0.406: v1(67.69,34.96) 67.69,35.24 C8.1 R11.2 C4.2 R9.1
VREF_1V8HSTL: length 4.4
  TOP w0.381: U1.M2 v1(46.51,36.46)
  BOTTOM w0.406: R1.1 R2.2 C3.1 C1.1 46.61,36.56 v1(46.51,36.46)
VREF_LPDDR2: length 4.7
  TOP w0.381: U1.D21 v1(66.52,45.47)
  BOTTOM w0.508: v1(66.52,45.47) 66.58,45.53 C9.1 R12.2 C6.2 R10.1
N31901: length 3
  TOP w0.147: v2(70.87,60.07) 71.14,60.35 U3.22
  BOTTOM w0.147: R119.2 v2(70.87,60.07) R118.1
N16765826: length 4
  BOTTOM w0.147: J5.4 8.47,35.39 9.08,36 R124.1
N16772990: length 1
  TOP w0.147: R143.2 41.4,46.86 41.47,46.8 C71.1
N16895577: length 2.2
  BOTTOM w0.147: U14.12 22.08,54 22.86,53.21 R206.2
N16895579: length 1.9
  BOTTOM w0.147: R209.2 16.87,53.72 17.14,54 U14.19
N16938690: length 10
  TOP w0.508: R217.2 8.19,25.91 SW3.2 SW3.5
N16938718: length 20.3
  BOTTOM w0.508: R264.1 R221.2 3.49,21.78 SW3.4 6.99,28.45 SW3.3
N16938802: length 2.6
  TOP w0.305: U18.5 25.84,17.46 26.04,17.65 C97.1
N16938806: length 2.8
  TOP w0.305: C99.1 26.16,18.67 25.59,18.1 U18.6
N16938884: length 0.9
  TOP w0.254: C98.2 R231.1
N16939009: length 4.2
  TOP w0.203: R225.1 15.24,20 15.24,22.99 15.45,23.2 U16.4
N16939055: length 3.6
  TOP w0.254: R222.1 12.7,16.89 12.88,16.71 14.68,16.71 14.86,16.89 V2.2
N16993273: length 6.6
  BOTTOM w0.203: U20.5 54.57,71.98 C105.2
  BOTTOM w0.305: R235.2 C105.2
N17581797: length 5.3
  TOP w0.203: v2(28.19,57.02) 28.3,57.13 U19.4
  BOTTOM w0.381: R291.2 C216.1 R290.1 28.96,56.77 28.7,57.02 v2(28.19,57.02)
N17604176: length 3.1
  TOP w0.305: v1(71.5,29.59) 71.56,29.65 C31.1 71.56,30.92 v1(71.5,30.99)
  BOTTOM w0.305: v1(71.5,30.99) R73.1 ; v1(71.5,29.59) R75.2
N17604218: length 2.8
  TOP w0.305: v1(71.63,32.26) R81.1 ; R83.2 v1(71.63,33.66)
  BOTTOM w0.305: v1(71.63,33.66) 71.56,33.59 C33.1 71.56,32.32 v1(71.63,32.26)
N17604268: length 2.8
  TOP w0.305: R88.1 v1(71.63,28.32) ; R90.2 v1(71.63,26.92)
  BOTTOM w0.305: v1(71.63,28.32) 71.56,28.26 C35.1 71.56,26.99 v1(71.63,26.92)
N17605267: length 2.9
  TOP w0.305: R76.2 v1(71.56,24.26) ; R74.1 v1(71.63,25.65)
  BOTTOM w0.305: v1(71.63,25.65) 71.56,25.59 C32.1 v1(71.56,24.26)
N17605327: length 2.8
  TOP w0.305: R82.1 v1(71.63,22.99) ; R84.2 v1(71.63,21.59)
  BOTTOM w0.305: v1(71.63,22.99) 71.56,22.92 C34.1 71.56,21.65 v1(71.63,21.59)
N17606282: length 2.8
  TOP w0.305: v1(56.13,21.97) 56.2,22.03 C37.1 57.47,22.03 v1(57.53,21.97)
  BOTTOM w0.305: R96.1 v1(57.53,21.97) ; R97.2 v1(56.13,21.97)
N17606316: length 2.8
  TOP w0.305: R104.1 v1(60.33,21.97) ; v1(58.93,21.97) R105.2
  BOTTOM w0.305: v1(58.93,21.97) 58.99,22.03 C40.1 60.26,22.03 v1(60.33,21.97)
N17606350: length 2.8
  TOP w0.305: R108.1 v1(54.86,21.97) ; R109.2 v1(53.47,21.97)
  BOTTOM w0.305: v1(53.47,21.97) 53.53,22.03 C41.1 54.8,22.03 v1(54.86,21.97)

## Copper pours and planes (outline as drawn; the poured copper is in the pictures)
1.2V_CORE on BOTTOM (solid shape): 41.78,37.97 43.31,37.97 43.56,37.72 43.56,37.08 42.93,36.45 40.26,36.45 40.01,36.7 40.01,38.35 41.4,38.35
1.2V_CORE on BOTTOM (solid shape): outline of 139 points within 16.26,32 23.75,34.92
1.2V_CORE on VCC03: 27.94,41.27 47.88,41.27 50.16,38.99 52.01,38.99 52.32,39.31 52.32,39.62 52.7,40 58.55,40 58.8,39.75 58.8,34.67 58.55,34.42 52.45,34.42 51.82,35.05 50.8,35.05 43.81,28.07 30.48,28.07 28.96,29.59 22.61,29.59 22.1,30.1 22.1,35.43
1.2V_CORE_SENSE on TOP (solid shape): 16.26,34.04 16.26,31.88 15.75,31.88 15.49,31.62 15.49,30.23 15.37,30.1 13.97,30.1 13.84,30.23 10.16,30.23 10.16,33.66 10.79,34.29 16,34.29
1.2V_CORE_SENSE on BOTTOM (solid shape): 15.49,34.04 15.49,30.35 15.24,30.1 14.1,30.1 13.97,30.23 10.16,30.23 10.16,30.35 15.24,30.35 15.24,30.73 14.86,30.73 14.86,30.35 14.61,30.35 14.61,30.73 14.22,30.73 14.22,30.35 10.16,30.35 10.16,30.99 13.97,30.99 13.97,31.5 13.46,31.5 13.46,30.99 12.7,30.99 12.7,31.5 12.19,31.5 12.19,30.99 10.16,30.99 10.16,33.66 10.79,34.29 15.24,34.29
1.2V_VCCD_PLL on BOTTOM (solid shape): 39.24,36.83 39.12,36.7 35.94,36.7 35.69,36.96 35.69,37.08 37.08,37.08 37.08,37.59 36.58,37.59 36.58,37.08 35.69,37.08 35.69,38.35 39.24,38.35
1.2V_VCCD_PLL on ART04: 46.86,38.1 54.74,38.1 56.9,40.26 57.15,40.26 57.53,39.88 59.05,39.88 59.05,34.92 57.53,34.92 55.24,37.21 44.83,37.21 43.81,36.2 38.1,36.2 37.34,36.96 37.34,38.1 37.59,38.35 46.61,38.35
1.2V_VCCIO on TOP (solid shape): 88.14,44.45 88.39,44.2 88.39,42.93 89.15,42.16 89.15,39.37 86.36,39.37 85.85,39.88 85.85,44.07 86.23,44.45
1.2V_VCCIO on BOTTOM (solid shape): 79.5,39.24 79.63,39.12 79.63,38.86 79.5,38.73 78.61,38.73 78.49,38.86 78.49,38.99 78.61,39.12 78.99,39.12 79.12,39.24 79.12,39.88 79.5,39.88
1.2V_VCCIO on BOTTOM (solid shape): 71.75,48.64 71.75,46.61 71.37,46.23 69.22,46.23 69.22,46.48 70.99,46.48 70.99,46.86 70.61,46.86 70.61,46.48 70.36,46.48 70.36,46.86 69.6,46.86 69.6,46.48 69.22,46.48 69.22,46.74 70.1,47.62 71.37,47.62 71.37,48.13 70.87,48.13 70.87,47.62 70.1,47.62 70.23,47.75 70.23,49.02 71.37,49.02
1.2V_VCCIO on BOTTOM (solid shape): 86.23,52.32 86.23,51.18 85.72,50.67 85.72,50.04 86.23,49.53 87.12,49.53 87.12,44.45 87.38,44.2 87.88,44.2 88.14,43.94 88.14,42.67 88.39,42.42 88.39,41.27 87.38,41.27 87.12,41.53 87.12,41.91 87,42.04 86.23,42.04 86.23,42.16 87.76,42.16 87.76,42.67 87.25,42.67 87.25,42.16 86.23,42.16 86.23,42.29 87,42.29 87,42.67 86.61,42.67 86.61,42.29 86.23,42.29 86.23,42.55 85.85,42.93 85.22,42.93 85.22,43.18 85.98,43.18 85.98,43.56 85.6,43.56 85.6,43.18 85.22,43.18 85.22,43.56 85.47,43.81 85.47,44.07 86.49,44.07 86.49,44.58 85.98,44.58 85.98,44.07 85.47,44.07 85.47,45.34 86.49,45.34 86.49,45.85 85.98,45.85 85.98,45.34 85.47,45.34 85.47,46.1 86.49,46.1 86.49,46.61 85.98,46.61 85.98,46.1 85.47,46.1 85.47,47.37 86.49,47.37 86.49,47.88 85.98,47.88 85.98,47.37 85.47,47.37 85.47,47.88 85.22,48.13 86.49,48.13 86.49,48.64 85.98,48.64 85.98,48.13 85.22,48.13 84.45,48.89 84.45,52.2 84.71,52.45 86.11,52.45
1.2V_VCCIO on BOTTOM: 88.14,32.64 88.01,32.51 88.01,27.18 87.12,26.29 87.12,24.13 87.88,24.13 89.15,25.4 89.15,32.64 ; 8 cut-outs
1.2V_VCCIO on VCC03: 59.18,35.43 59.18,40.77 63.5,45.09 66.04,45.09 72.39,51.43 88.52,51.43 88.65,51.31 88.65,37.85 88.39,37.59 85.34,37.59 84.84,37.08 84.84,35.05 85.47,34.42 92.2,34.42 92.33,34.29 92.33,28.32 92.2,28.19 87.5,28.19 82.93,32.77 61.85,32.77 ; 1 cut-out
1.8V on BOTTOM (solid shape): 27.56,31.5 27.56,29.46 27.81,29.21 27.81,27.69 27.56,27.43 26.67,27.43 26.42,27.69 26.42,30.99 27.18,30.99 27.18,31.37 26.8,31.37 26.8,30.99 26.42,30.99 26.42,31.62 27.43,31.62
1.8V on BOTTOM (solid shape): outline of 204 points within 54.99,29.08 92.33,73.28
1.8V on TOP: 8.26,59.69 8,59.94 8,66.42 8.26,66.67 8.26,74.17 9.14,75.06 55.63,75.06 57.15,73.53 57.15,70.87 56.9,70.61 56.39,70.61 55.24,71.75 45.72,71.75 45.09,71.12 42.55,71.12 41.91,71.75 40.64,71.75 40.01,71.12 32.77,71.12 32,71.88 30.35,71.88 28.83,73.41 28.32,73.41 27.3,72.39 27.3,72.01 26.67,71.37 16,71.37 14.1,73.28 12.19,73.28 10.16,71.25 10.16,59.94 9.91,59.69
1.8V on BOTTOM: 50.16,32.89 46.61,32.89 44.58,34.92 44.58,35.56 45.97,35.56 45.97,35.05 46.1,34.92 47.24,34.92 48.51,36.2 51.18,36.2 51.82,35.56 51.82,34.54 ; 1 cut-out
1.8V on VCC03: 51.05,34.8 51.82,34.8 52.96,33.66 52.96,27.05 46.99,21.08 46.99,20.07 41.27,14.35 31.88,14.35 30.99,13.46 26.54,13.46 25.4,14.61 25.4,28.7 25.78,29.08 28.7,29.08 30.23,27.56 43.81,27.56
1.8V on ART04: 24.77,36.2 24.77,38.23 20.7,42.29 16.38,42.29 10.29,48.39 10.29,53.21 12.45,55.37 13.08,55.37 13.59,54.86 13.59,54.1 13.84,53.85 14.1,53.85 15.24,54.99 15.24,59.05 12.95,61.34 8.26,61.34 7.87,60.96 7.87,47.75 16.38,39.24 19.68,39.24 22.22,36.7 22.22,35.94 25.15,33.02 25.15,28.19 25.91,27.43 27.56,27.43 27.81,27.69 27.81,33.15
